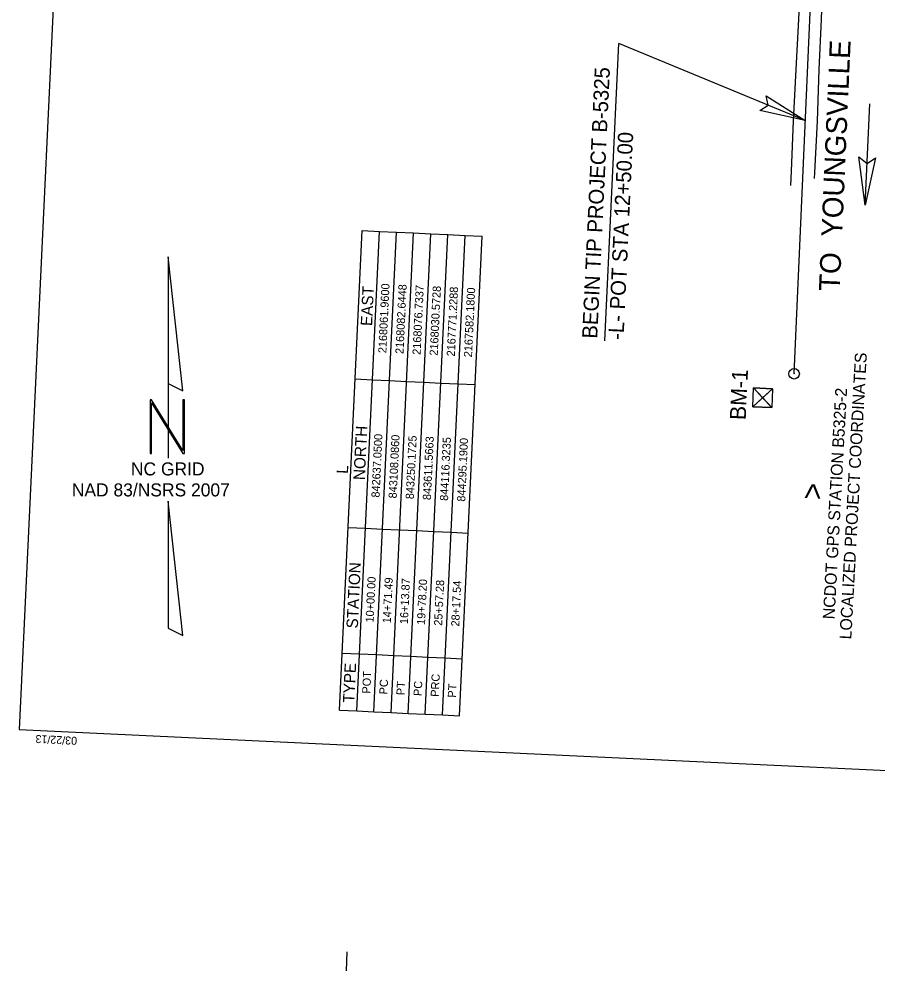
# Model space of a CAD drawing. Extents: x 2167298 to 2168977, y 841960 to 844561.
# Drawn here: x 2167298 to 2168145, y 842048 to 842987 of the extents above; entities that cross this region are included whole.
import ezdxf

# ---------------------------------------------------------------- set-up
doc = ezdxf.new("R2010")
doc.units = 0
for name, color, linetype in [('CTL Bench Mark CELL', 7, 'Continuous'), ('CTL Bench Mark Text', 7, 'Continuous'), ('CTL GPS Vertical Text', 7, 'Continuous'), ('CTL North Arrow NAD 83 NSRS 2007 CELL', 7, 'Continuous'), ('CTL Sheet Border CELL', 7, 'Continuous'), ('CTL Sheet Notes CELL', 7, 'Continuous'), ('CTL Sheet Table Cell', 7, 'Continuous'), ('CTL Sheet Text', 7, 'Continuous'), ('Default', 7, 'Continuous'), ('Exist Roads EOP', 7, 'Continuous'), ('Prop Horizontal Alignment', 7, 'Continuous'), ('Typical Terminator CELL', 7, 'Continuous')]:
    doc.layers.add(name, color=color, linetype=linetype)

# ---------------------------------------------------------------- blocks, each defined once
blk = doc.blocks.new('TERMINATOR')
at = {"layer": 'Typical Terminator CELL'}
blk.add_lwpolyline([(-0.4687, 0.0807), (0, 0), (-0.4713, -0.0833), (-0.4114, 0)], close=True, dxfattribs=at)

msp = doc.modelspace()

# ---------------------------------------------------------------- linework, layer by layer
at = {"layer": 'CTL Bench Mark CELL'}
msp.add_line((2168030.92, 842613.4), (2168030.92, 842613.4), dxfattribs=at)
msp.add_lwpolyline([(2168022.02, 842623.12), (2168040.64, 842622.27), (2168039.79, 842603.64), (2168021.16, 842604.5)], close=True, dxfattribs=at)
for points in [[(2168040.64, 842622.27), (2168021.16, 842604.5), (2168030.9, 842613.38), (2168039.79, 842603.64), (2168022.02, 842623.12)], [(2168030.9, 842613.38), (2168040.64, 842622.27), (2168022.02, 842623.12), (2168030.9, 842613.38)], [(2168030.9, 842613.38), (2168021.16, 842604.5), (2168039.79, 842603.64), (2168030.9, 842613.38)]]:
    msp.add_lwpolyline(points, dxfattribs=at)
at = {"layer": 'CTL North Arrow NAD 83 NSRS 2007 CELL'}
msp.add_line((2167444.79, 842565.36), (2167444.79, 842565.36), dxfattribs=at)
for points in [[(2167444.47, 842752.47), (2167444.47, 842627.44), (2167459.2, 842620.08)], [(2167426.84, 842558.37), (2167428.31, 842558.37), (2167428.31, 842608.37), (2167459.2, 842558.37), (2167460.68, 842558.37), (2167460.68, 842611.29), (2167459.2, 842611.29), (2167459.2, 842561.29), (2167428.31, 842611.29), (2167426.84, 842611.29)], [(2167444.47, 842386.26), (2167459.2, 842378.95), (2167444.47, 842511.29)]]:
    msp.add_lwpolyline(points, close=True, dxfattribs=at)
msp.add_lwpolyline([(2167444.47, 842627.44), (2167444.47, 842553.92)], dxfattribs=at)
at = {"layer": 'CTL Sheet Border CELL'}
msp.add_line((2167620.38, 842048.09), (2167621.26, 842066.81), dxfattribs=at)
msp.add_lwpolyline([(2167403.66, 844533.83), (2167297.51, 842286.33), (2168870.75, 842212.02), (2168976.9, 844459.52)], close=True, dxfattribs=at)
at = {"layer": 'CTL Sheet Table Cell'}
for p, q in [((2167613.7, 842305.34), (2167636.04, 842778.3)), ((2167630.59, 842304.54), (2167652.93, 842777.5)), ((2167636.04, 842778.3), (2167652.93, 842777.5)), ((2167647.48, 842303.74), (2167669.82, 842776.71)), ((2167652.93, 842777.5), (2167669.82, 842776.71)), ((2167664.37, 842302.95), (2167686.71, 842775.91)), ((2167669.82, 842776.71), (2167686.71, 842775.91)), ((2167681.26, 842302.15), (2167703.6, 842775.11)), ((2167686.71, 842775.91), (2167703.6, 842775.11)), ((2167698.16, 842301.35), (2167720.49, 842774.31)), ((2167703.6, 842775.11), (2167720.49, 842774.31)), ((2167720.49, 842774.31), (2167737.39, 842773.51)), ((2167715.05, 842300.55), (2167737.39, 842773.51)), ((2167731.94, 842299.75), (2167754.28, 842772.72)), ((2167737.39, 842773.51), (2167754.28, 842772.72)), ((2167629.12, 842631.91), (2167646.01, 842631.11)), ((2167646.01, 842631.11), (2167662.91, 842630.31)), ((2167662.91, 842630.31), (2167679.8, 842629.51)), ((2167679.8, 842629.51), (2167696.69, 842628.72)), ((2167696.69, 842628.72), (2167713.58, 842627.92)), ((2167713.58, 842627.92), (2167730.47, 842627.12)), ((2167730.47, 842627.12), (2167747.36, 842626.32)), ((2167622.21, 842485.51), (2167639.1, 842484.72)), ((2167639.1, 842484.72), (2167655.99, 842483.92)), ((2167655.99, 842483.92), (2167672.88, 842483.12)), ((2167672.88, 842483.12), (2167689.77, 842482.32)), ((2167689.77, 842482.32), (2167706.67, 842481.53)), ((2167706.67, 842481.53), (2167723.56, 842480.73)), ((2167723.56, 842480.73), (2167740.45, 842479.93)), ((2167616.36, 842361.64), (2167633.25, 842360.85)), ((2167633.25, 842360.85), (2167650.14, 842360.05)), ((2167650.14, 842360.05), (2167667.03, 842359.25)), ((2167667.03, 842359.25), (2167683.92, 842358.45)), ((2167683.92, 842358.45), (2167700.82, 842357.65)), ((2167700.82, 842357.65), (2167717.71, 842356.86)), ((2167717.71, 842356.86), (2167734.6, 842356.06)), ((2167613.7, 842305.34), (2167630.59, 842304.54)), ((2167630.59, 842304.54), (2167647.48, 842303.74)), ((2167647.48, 842303.74), (2167664.37, 842302.95)), ((2167664.37, 842302.95), (2167681.26, 842302.15)), ((2167681.26, 842302.15), (2167698.16, 842301.35)), ((2167698.16, 842301.35), (2167715.05, 842300.55)), ((2167715.05, 842300.55), (2167731.94, 842299.75))]:
    msp.add_line(p, q, dxfattribs=at)
at = {"layer": 'Default'}
for p, q in [((2167875.09, 842669.55), (2167888.93, 842962.65)), ((2168072.93, 842886.81), (2167888.93, 842962.65)), ((2168131.89, 842803.47), (2168136.61, 842903.36))]:
    msp.add_line(p, q, dxfattribs=at)
at = {"layer": 'Exist Roads EOP'}
for points in [[(2168058.72, 842822.88), (2168059.29, 842836.83), (2168061.43, 842886.56), (2168063.83, 842937.15), (2168066.47, 842986.79), (2168068.78, 843034.77)], [(2168058.72, 842822.88), (2168059.29, 842836.83), (2168061.43, 842886.56), (2168063.83, 842937.15), (2168066.47, 842986.79), (2168068.78, 843034.77)], [(2168082.14, 842829.64), (2168082.38, 842835.39), (2168084.85, 842886.27), (2168086.71, 842937.1), (2168088.8, 842986.5), (2168090.54, 843034.94)], [(2168082.14, 842829.64), (2168082.38, 842835.39), (2168084.85, 842886.27), (2168086.71, 842937.1), (2168088.8, 842986.5), (2168090.54, 843034.94)]]:
    msp.add_lwpolyline(points, dxfattribs=at)
at = {"layer": 'Prop Horizontal Alignment'}
msp.add_line((2168061.96, 842637.05), (2168082.64, 843108.09), dxfattribs=at)
for radius in [5.19, 0.167]:
    msp.add_circle((2168061.96, 842637.05), radius, dxfattribs=at)

# ---------------------------------------------------------------- block references
at = {"layer": 'Default'}
for p, xscale, yscale, rotation in [((2168072.93, 842886.81), 96.00000000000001, 96.00000000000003, -22.401339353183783), ((2168131.89, 842803.47), 100.00000000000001, 99.99999999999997, -92.70325283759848)]:
    msp.add_blockref('TERMINATOR', p, dxfattribs=dict(at, xscale=xscale, yscale=yscale, rotation=rotation))

# ---------------------------------------------------------------- texts
at = {"layer": 'CTL Bench Mark Text'}
msp.add_text('BM-1', height=15.692, rotation=87.29593, dxfattribs=at).set_placement((2168014.14, 842591.14))
at = {"layer": 'CTL GPS Vertical Text'}
for s, p in [('LOCALIZED PROJECT COORDINATES', (2168118.29, 842374.87)), ('NCDOT GPS STATION B5325-2', (2168101.8, 842394.67))]:
    msp.add_text(s, height=11.6923, rotation=86.87788, dxfattribs=at).set_placement(p)
at = {"layer": 'CTL North Arrow NAD 83 NSRS 2007 CELL'}
for s, height, p in [('NC GRID', 12.862, (2167407.86, 842536.78)), ('NAD 83/NSRS 2007', 12.8615, (2167349.58, 842516.1))]:
    msp.add_text(s, height=height, dxfattribs=at).set_placement(p)
at = {"layer": 'CTL Sheet Border CELL'}
msp.add_text('03/22/13', height=7.875, rotation=177.29593, dxfattribs=at).set_placement((2167354.93, 842278.91))
at = {"layer": 'CTL Sheet Notes CELL'}
for s, height, rotation, p in [('EAST', 11.274, 87.29593, (2167645.69, 842683.96)), ('NORTH', 11.274, 87.29593, (2167638.51, 842531.98)), ('L', 11.27, 87.29593, (2167621.88, 842538.23)), ('>', 21.23, 87.1906, (2168090.14, 842512.27)), ('STATION', 11.274, 87.29593, (2167631.6, 842385.67)), ('TYPE', 11.274, 87.29593, (2167628.14, 842312.34))]:
    msp.add_text(s, height=height, rotation=rotation, dxfattribs=at).set_placement(p)
at = {"layer": 'CTL Sheet Text'}
for s, height, p in [('2168061.9600', 8.0526, (2167659.74, 842657.17)), ('2168082.6448', 8.0526, (2167676.63, 842656.37)), ('2168076.7337', 8.0526, (2167693.52, 842655.57)), ('2168030.5728', 8.0526, (2167710.41, 842654.77)), ('2167771.2288', 8.0526, (2167727.31, 842653.98)), ('2167582.1800', 8.0526, (2167744.2, 842653.18)), ('842637.0500', 8.0526, (2167653.01, 842514.76)), ('843108.0860', 8.0526, (2167669.91, 842513.97)), ('843250.1725', 8.0526, (2167686.8, 842513.17)), ('843611.5663', 8.0526, (2167703.69, 842512.37)), ('844116.3235', 8.0526, (2167720.58, 842511.57)), ('844295.1900', 8.0526, (2167737.47, 842510.77)), ('10+00.00', 8.053, (2167647.2, 842391.6)), ('14+71.49', 8.053, (2167664.09, 842390.8)), ('16+13.87', 8.053, (2167680.98, 842390.01)), ('19+78.20', 8.053, (2167697.87, 842389.21)), ('25+57.28', 8.053, (2167714.76, 842388.41)), ('28+17.54', 8.053, (2167731.65, 842387.61)), ('POT', 8.053, (2167643.88, 842321.46)), ('PC ', 8.053, (2167660.78, 842320.67)), ('PT ', 8.053, (2167677.67, 842319.87)), ('PC ', 8.053, (2167694.56, 842319.07)), ('PRC', 8.053, (2167711.45, 842318.27)), ('PT ', 8.053, (2167728.34, 842317.48))]:
    msp.add_text(s, height=height, rotation=87.29593, dxfattribs=at).set_placement(p)
at = {"layer": 'Default'}
for s, height, rotation, p in [('TO  YOUNGSVILLE', 20.57, 87.48556, (2168106.89, 842718.25)), ('BEGIN TIP PROJECT B-5325', 14.96, 87.29593, (2167867.71, 842671.47)), ('-L- POT STA 12+50.00', 14.96, 87.29593, (2167893.65, 842670.25))]:
    msp.add_text(s, height=height, rotation=rotation, dxfattribs=at).set_placement(p)

doc.saveas('drawing.dxf')
